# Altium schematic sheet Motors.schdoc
size 298 x 624 mm
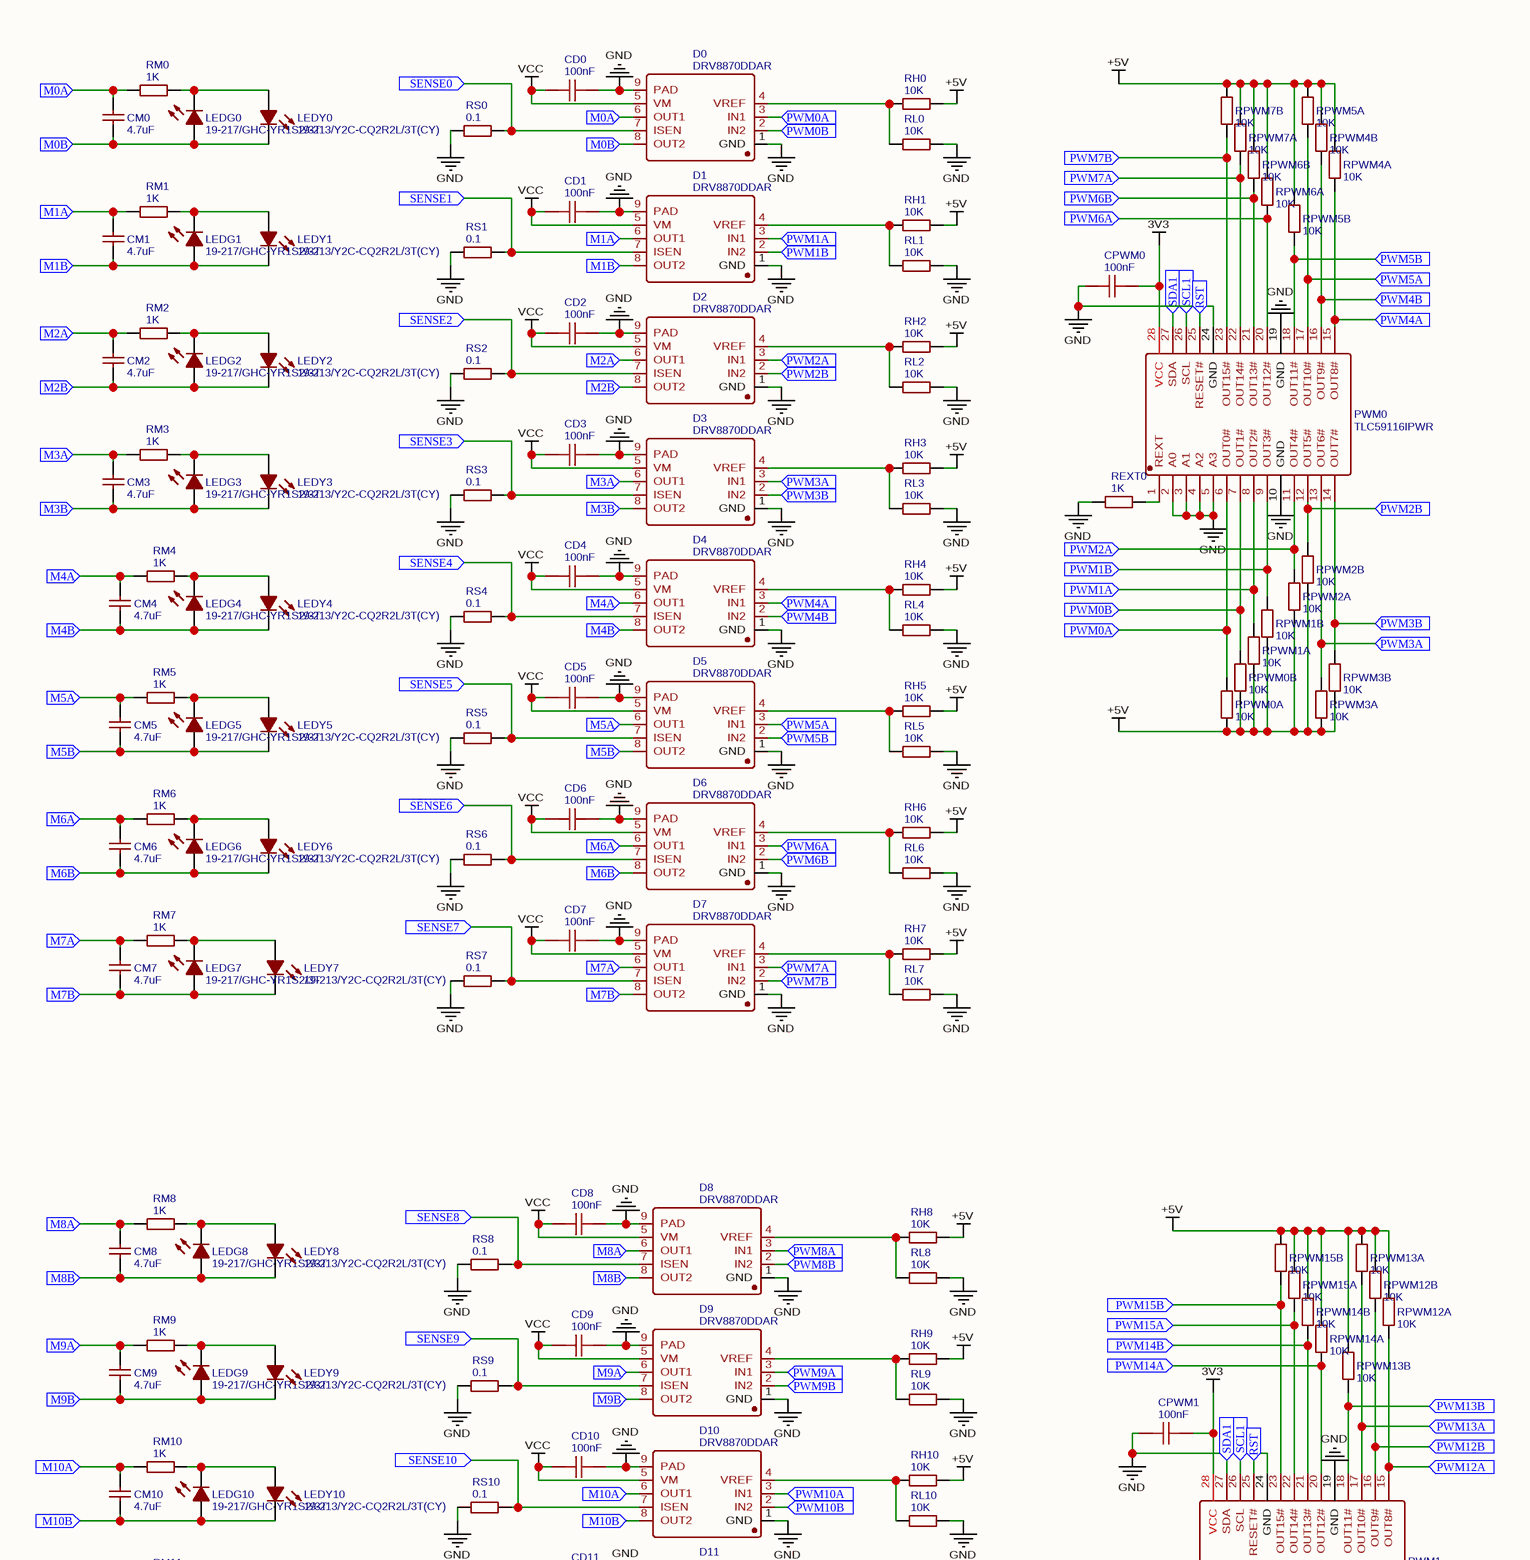
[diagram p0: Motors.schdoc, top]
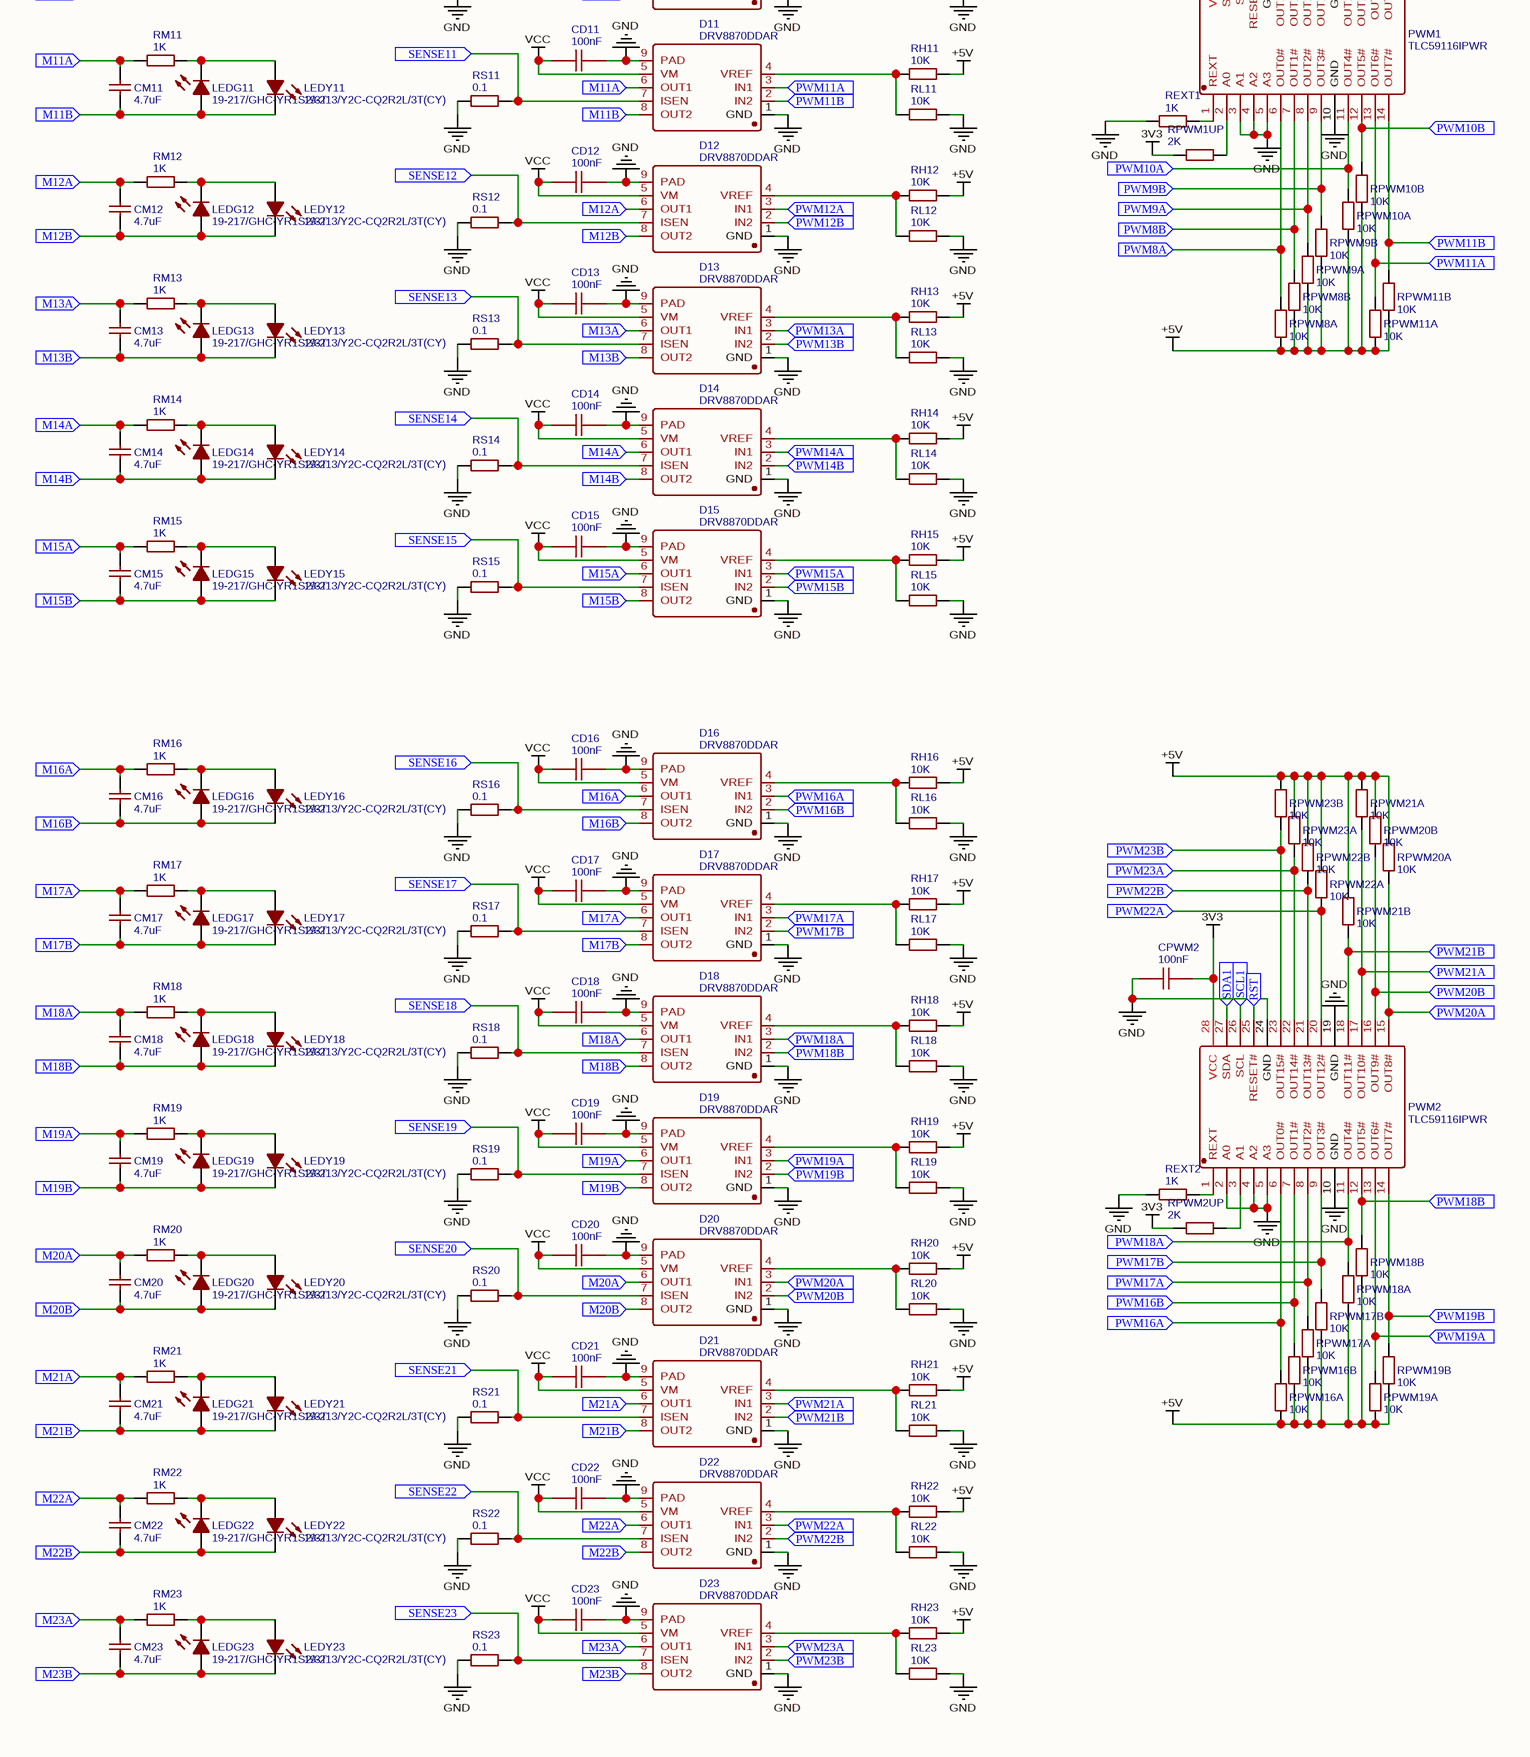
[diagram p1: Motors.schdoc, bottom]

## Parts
CD0  100nF  [0603]
CD1  100nF  [0603]
CD2  100nF  [0603]
CD3  100nF  [0603]
CD4  100nF  [0603]
CD5  100nF  [0603]
CD6  100nF  [0603]
CD7  100nF  [0603]
CD8  100nF  [0603]
CD9  100nF  [0603]
CD10  100nF  [0603]
CD11  100nF  [0603]
CD12  100nF  [0603]
CD13  100nF  [0603]
CD14  100nF  [0603]
CD15  100nF  [0603]
CD16  100nF  [0603]
CD17  100nF  [0603]
CD18  100nF  [0603]
CD19  100nF  [0603]
CD20  100nF  [0603]
CD21  100nF  [0603]
CD22  100nF  [0603]
CD23  100nF  [0603]
CM0  4.7uF  [1206]
CM1  4.7uF  [1206]
CM2  4.7uF  [1206]
CM3  4.7uF  [1206]
CM4  4.7uF  [1206]
CM5  4.7uF  [1206]
CM6  4.7uF  [1206]
CM7  4.7uF  [1206]
CM8  4.7uF  [1206]
CM9  4.7uF  [1206]
CM10  4.7uF  [1206]
CM11  4.7uF  [1206]
CM12  4.7uF  [1206]
CM13  4.7uF  [1206]
CM14  4.7uF  [1206]
CM15  4.7uF  [1206]
CM16  4.7uF  [1206]
CM17  4.7uF  [1206]
CM18  4.7uF  [1206]
CM19  4.7uF  [1206]
CM20  4.7uF  [1206]
CM21  4.7uF  [1206]
CM22  4.7uF  [1206]
CM23  4.7uF  [1206]
CPWM0  100nF  [0603]
CPWM1  100nF  [0603]
CPWM2  100nF  [0603]
D0  DRV8870DDAR  [HSOP-8_L5.0-W4.0-P1.27-LS6.2-BL-EP]
D1  DRV8870DDAR  [HSOP-8_L5.0-W4.0-P1.27-LS6.2-BL-EP]
D2  DRV8870DDAR  [HSOP-8_L5.0-W4.0-P1.27-LS6.2-BL-EP]
D3  DRV8870DDAR  [HSOP-8_L5.0-W4.0-P1.27-LS6.2-BL-EP]
D4  DRV8870DDAR  [HSOP-8_L5.0-W4.0-P1.27-LS6.2-BL-EP]
D5  DRV8870DDAR  [HSOP-8_L5.0-W4.0-P1.27-LS6.2-BL-EP]
D6  DRV8870DDAR  [HSOP-8_L5.0-W4.0-P1.27-LS6.2-BL-EP]
D7  DRV8870DDAR  [HSOP-8_L5.0-W4.0-P1.27-LS6.2-BL-EP]
D8  DRV8870DDAR  [HSOP-8_L5.0-W4.0-P1.27-LS6.2-BL-EP]
D9  DRV8870DDAR  [HSOP-8_L5.0-W4.0-P1.27-LS6.2-BL-EP]
D10  DRV8870DDAR  [HSOP-8_L5.0-W4.0-P1.27-LS6.2-BL-EP]
D11  DRV8870DDAR  [HSOP-8_L5.0-W4.0-P1.27-LS6.2-BL-EP]
D12  DRV8870DDAR  [HSOP-8_L5.0-W4.0-P1.27-LS6.2-BL-EP]
D13  DRV8870DDAR  [HSOP-8_L5.0-W4.0-P1.27-LS6.2-BL-EP]
D14  DRV8870DDAR  [HSOP-8_L5.0-W4.0-P1.27-LS6.2-BL-EP]
D15  DRV8870DDAR  [HSOP-8_L5.0-W4.0-P1.27-LS6.2-BL-EP]
D16  DRV8870DDAR  [HSOP-8_L5.0-W4.0-P1.27-LS6.2-BL-EP]
D17  DRV8870DDAR  [HSOP-8_L5.0-W4.0-P1.27-LS6.2-BL-EP]
D18  DRV8870DDAR  [HSOP-8_L5.0-W4.0-P1.27-LS6.2-BL-EP]
D19  DRV8870DDAR  [HSOP-8_L5.0-W4.0-P1.27-LS6.2-BL-EP]
D20  DRV8870DDAR  [HSOP-8_L5.0-W4.0-P1.27-LS6.2-BL-EP]
D21  DRV8870DDAR  [HSOP-8_L5.0-W4.0-P1.27-LS6.2-BL-EP]
D22  DRV8870DDAR  [HSOP-8_L5.0-W4.0-P1.27-LS6.2-BL-EP]
D23  DRV8870DDAR  [HSOP-8_L5.0-W4.0-P1.27-LS6.2-BL-EP]
LEDG0  19-217/GHC-YR1S2/3T  [LED0603-R-RD]
LEDG1  19-217/GHC-YR1S2/3T  [LED0603-R-RD]
LEDG2  19-217/GHC-YR1S2/3T  [LED0603-R-RD]
LEDG3  19-217/GHC-YR1S2/3T  [LED0603-R-RD]
LEDG4  19-217/GHC-YR1S2/3T  [LED0603-R-RD]
LEDG5  19-217/GHC-YR1S2/3T  [LED0603-R-RD]
LEDG6  19-217/GHC-YR1S2/3T  [LED0603-R-RD]
LEDG7  19-217/GHC-YR1S2/3T  [LED0603-R-RD]
LEDG8  19-217/GHC-YR1S2/3T  [LED0603-R-RD]
LEDG9  19-217/GHC-YR1S2/3T  [LED0603-R-RD]
LEDG10  19-217/GHC-YR1S2/3T  [LED0603-R-RD]
LEDG11  19-217/GHC-YR1S2/3T  [LED0603-R-RD]
LEDG12  19-217/GHC-YR1S2/3T  [LED0603-R-RD]
LEDG13  19-217/GHC-YR1S2/3T  [LED0603-R-RD]
LEDG14  19-217/GHC-YR1S2/3T  [LED0603-R-RD]
LEDG15  19-217/GHC-YR1S2/3T  [LED0603-R-RD]
LEDG16  19-217/GHC-YR1S2/3T  [LED0603-R-RD]
LEDG17  19-217/GHC-YR1S2/3T  [LED0603-R-RD]
LEDG18  19-217/GHC-YR1S2/3T  [LED0603-R-RD]
LEDG19  19-217/GHC-YR1S2/3T  [LED0603-R-RD]
LEDG20  19-217/GHC-YR1S2/3T  [LED0603-R-RD]
LEDG21  19-217/GHC-YR1S2/3T  [LED0603-R-RD]
LEDG22  19-217/GHC-YR1S2/3T  [LED0603-R-RD]
LEDG23  19-217/GHC-YR1S2/3T  [LED0603-R-RD]
LEDY0  19-213/Y2C-CQ2R2L/3T(CY)  [LED0603-R-RD]
LEDY1  19-213/Y2C-CQ2R2L/3T(CY)  [LED0603-R-RD]
LEDY2  19-213/Y2C-CQ2R2L/3T(CY)  [LED0603-R-RD]
LEDY3  19-213/Y2C-CQ2R2L/3T(CY)  [LED0603-R-RD]
LEDY4  19-213/Y2C-CQ2R2L/3T(CY)  [LED0603-R-RD]
LEDY5  19-213/Y2C-CQ2R2L/3T(CY)  [LED0603-R-RD]
LEDY6  19-213/Y2C-CQ2R2L/3T(CY)  [LED0603-R-RD]
LEDY7  19-213/Y2C-CQ2R2L/3T(CY)  [LED0603-R-RD]
LEDY8  19-213/Y2C-CQ2R2L/3T(CY)  [LED0603-R-RD]
LEDY9  19-213/Y2C-CQ2R2L/3T(CY)  [LED0603-R-RD]
LEDY10  19-213/Y2C-CQ2R2L/3T(CY)  [LED0603-R-RD]
LEDY11  19-213/Y2C-CQ2R2L/3T(CY)  [LED0603-R-RD]
LEDY12  19-213/Y2C-CQ2R2L/3T(CY)  [LED0603-R-RD]
LEDY13  19-213/Y2C-CQ2R2L/3T(CY)  [LED0603-R-RD]
LEDY14  19-213/Y2C-CQ2R2L/3T(CY)  [LED0603-R-RD]
LEDY15  19-213/Y2C-CQ2R2L/3T(CY)  [LED0603-R-RD]
LEDY16  19-213/Y2C-CQ2R2L/3T(CY)  [LED0603-R-RD]
LEDY17  19-213/Y2C-CQ2R2L/3T(CY)  [LED0603-R-RD]
LEDY18  19-213/Y2C-CQ2R2L/3T(CY)  [LED0603-R-RD]
LEDY19  19-213/Y2C-CQ2R2L/3T(CY)  [LED0603-R-RD]
LEDY20  19-213/Y2C-CQ2R2L/3T(CY)  [LED0603-R-RD]
LEDY21  19-213/Y2C-CQ2R2L/3T(CY)  [LED0603-R-RD]
LEDY22  19-213/Y2C-CQ2R2L/3T(CY)  [LED0603-R-RD]
LEDY23  19-213/Y2C-CQ2R2L/3T(CY)  [LED0603-R-RD]
PWM0  TLC59116IPWR  [TSSOP-28_L9.8-W3.0-P0.66-LS6.4-BL]
PWM1  TLC59116IPWR  [TSSOP-28_L9.8-W3.0-P0.66-LS6.4-BL]
PWM2  TLC59116IPWR  [TSSOP-28_L9.8-W3.0-P0.66-LS6.4-BL]
REXT0  1K  [0603]
REXT1  1K  [0603]
REXT2  1K  [0603]
RH0  10K  [0603]
RH1  10K  [0603]
RH2  10K  [0603]
RH3  10K  [0603]
RH4  10K  [0603]
RH5  10K  [0603]
RH6  10K  [0603]
RH7  10K  [0603]
RH8  10K  [0603]
RH9  10K  [0603]
RH10  10K  [0603]
RH11  10K  [0603]
RH12  10K  [0603]
RH13  10K  [0603]
RH14  10K  [0603]
RH15  10K  [0603]
RH16  10K  [0603]
RH17  10K  [0603]
RH18  10K  [0603]
RH19  10K  [0603]
RH20  10K  [0603]
RH21  10K  [0603]
RH22  10K  [0603]
RH23  10K  [0603]
RL0  10K  [0603]
RL1  10K  [0603]
RL2  10K  [0603]
RL3  10K  [0603]
RL4  10K  [0603]
RL5  10K  [0603]
RL6  10K  [0603]
RL7  10K  [0603]
RL8  10K  [0603]
RL9  10K  [0603]
RL10  10K  [0603]
RL11  10K  [0603]
RL12  10K  [0603]
RL13  10K  [0603]
RL14  10K  [0603]
RL15  10K  [0603]
RL16  10K  [0603]
RL17  10K  [0603]
RL18  10K  [0603]
RL19  10K  [0603]
RL20  10K  [0603]
RL21  10K  [0603]
RL22  10K  [0603]
RL23  10K  [0603]
RM0  1K  [0603]
RM1  1K  [0603]
RM2  1K  [0603]
RM3  1K  [0603]
RM4  1K  [0603]
RM5  1K  [0603]
RM6  1K  [0603]
RM7  1K  [0603]
RM8  1K  [0603]
RM9  1K  [0603]
RM10  1K  [0603]
RM11  1K  [0603]
RM12  1K  [0603]
RM13  1K  [0603]
RM14  1K  [0603]
RM15  1K  [0603]
RM16  1K  [0603]
RM17  1K  [0603]
RM18  1K  [0603]
RM19  1K  [0603]
RM20  1K  [0603]
RM21  1K  [0603]
RM22  1K  [0603]
RM23  1K  [0603]
RPWM0A  10K  [0603]
RPWM0B  10K  [0603]
RPWM1A  10K  [0603]
RPWM1B  10K  [0603]
RPWM1UP  2K  [0603]
RPWM2A  10K  [0603]
RPWM2B  10K  [0603]
RPWM2UP  2K  [0603]
RPWM3A  10K  [0603]
RPWM3B  10K  [0603]
RPWM4A  10K  [0603]
RPWM4B  10K  [0603]
RPWM5A  10K  [0603]
RPWM5B  10K  [0603]
RPWM6A  10K  [0603]
RPWM6B  10K  [0603]
RPWM7A  10K  [0603]
RPWM7B  10K  [0603]
RPWM8A  10K  [0603]
RPWM8B  10K  [0603]
RPWM9A  10K  [0603]
RPWM9B  10K  [0603]
RPWM10A  10K  [0603]
RPWM10B  10K  [0603]
RPWM11A  10K  [0603]
RPWM11B  10K  [0603]
RPWM12A  10K  [0603]
RPWM12B  10K  [0603]
RPWM13A  10K  [0603]
RPWM13B  10K  [0603]
RPWM14A  10K  [0603]
RPWM14B  10K  [0603]
RPWM15A  10K  [0603]
RPWM15B  10K  [0603]
RPWM16A  10K  [0603]
RPWM16B  10K  [0603]
RPWM17A  10K  [0603]
RPWM17B  10K  [0603]
RPWM18A  10K  [0603]
RPWM18B  10K  [0603]
RPWM19A  10K  [0603]
RPWM19B  10K  [0603]
RPWM20A  10K  [0603]
RPWM20B  10K  [0603]
RPWM21A  10K  [0603]
RPWM21B  10K  [0603]
RPWM22A  10K  [0603]
RPWM22B  10K  [0603]
RPWM23A  10K  [0603]
RPWM23B  10K  [0603]
RS0  0.1  [2512]
RS1  0.1  [2512]
RS2  0.1  [2512]
RS3  0.1  [2512]
RS4  0.1  [2512]
RS5  0.1  [2512]
RS6  0.1  [2512]
RS7  0.1  [2512]
RS8  0.1  [2512]
RS9  0.1  [2512]
RS10  0.1  [2512]
RS11  0.1  [2512]
RS12  0.1  [2512]
RS13  0.1  [2512]
RS14  0.1  [2512]
RS15  0.1  [2512]
RS16  0.1  [2512]
RS17  0.1  [2512]
RS18  0.1  [2512]
RS19  0.1  [2512]
RS20  0.1  [2512]
RS21  0.1  [2512]
RS22  0.1  [2512]
RS23  0.1  [2512]

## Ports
M0A, M0B, M1A, M1B, M2A, M2B, M3A, M3B, M4A, M4B, M5A, M5B, M6A, M6B, M7A, M7B, M8A, M8B, M9A, M9B, M10A, M10B, M11A, M11B, M12A, M12B, M13A, M13B, M14A, M14B, M15A, M15B, M16A, M16B, M17A, M17B, M18A, M18B, M19A, M19B, M20A, M20B, M21A, M21B, M22A, M22B, M23A, M23B, PWM0A, PWM0B, PWM1A, PWM1B, PWM2A, PWM2B, PWM3A, PWM3B, PWM4A, PWM4B, PWM5A, PWM5B, PWM6A, PWM6B, PWM7A, PWM7B, PWM8A, PWM8B, PWM9A, PWM9B, PWM10A, PWM10B, PWM11A, PWM11B, PWM12A, PWM12B, PWM13A, PWM13B, PWM14A, PWM14B, PWM15A, PWM15B, PWM16A, PWM16B, PWM17A, PWM17B, PWM18A, PWM18B, PWM19A, PWM19B, PWM20A, PWM20B, PWM21A, PWM21B, PWM22A, PWM22B, PWM23A, PWM23B, RST, SCL1, SDA1, SENSE0, SENSE1, SENSE2, SENSE3, SENSE4, SENSE5, SENSE6, SENSE7, SENSE8, SENSE9, SENSE10, SENSE11, SENSE12, SENSE13, SENSE14, SENSE15, SENSE16, SENSE17, SENSE18, SENSE19, SENSE20, SENSE21, SENSE22, SENSE23

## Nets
3V3: CPWM0.1 CPWM1.1 CPWM2.1 PWM0.28(VCC) PWM1.28(VCC) PWM2.28(VCC) RPWM1UP.2 RPWM2UP.2
+5V: RH0.2 RH1.2 RH2.2 RH3.2 RH4.2 RH5.2 RH6.2 RH7.2 RH8.2 RH9.2 RH10.2 RH11.2 RH12.2 RH13.2 RH14.2 RH15.2 RH16.2 RH17.2 RH18.2 RH19.2 RH20.2 RH21.2 RH22.2 RH23.2 RPWM0A.1 RPWM0B.1 RPWM1A.1 RPWM1B.1 RPWM2A.1 RPWM2B.1 RPWM3A.1 RPWM3B.1 RPWM4A.2 RPWM4B.2 RPWM5A.2 RPWM5B.2 RPWM6A.2 RPWM6B.2 RPWM7A.2 RPWM7B.2 RPWM8A.1 RPWM8B.1 RPWM9A.1 RPWM9B.1 RPWM10A.1 RPWM10B.1 RPWM11A.1 RPWM11B.1 RPWM12A.2 RPWM12B.2 RPWM13A.2 RPWM13B.2 RPWM14A.2 RPWM14B.2 RPWM15A.2 RPWM15B.2 RPWM16A.1 RPWM16B.1 RPWM17A.1 RPWM17B.1 RPWM18A.1 RPWM18B.1 RPWM19A.1 RPWM19B.1 RPWM20A.2 RPWM20B.2 RPWM21A.2 RPWM21B.2 RPWM22A.2 RPWM22B.2 RPWM23A.2 RPWM23B.2
GND: CD0.1 CD1.1 CD2.1 CD3.1 CD4.1 CD5.1 CD6.1 CD7.1 CD8.1 CD9.1 CD10.1 CD11.1 CD12.1 CD13.1 CD14.1 CD15.1 CD16.1 CD17.1 CD18.1 CD19.1 CD20.1 CD21.1 CD22.1 CD23.1 CPWM0.2 CPWM1.2 CPWM2.2 D0.1(GND) D0.9(PAD) D1.1(GND) D1.9(PAD) D2.1(GND) D2.9(PAD) D3.1(GND) D3.9(PAD) D4.1(GND) D4.9(PAD) D5.1(GND) D5.9(PAD) D6.1(GND) D6.9(PAD) D7.1(GND) D7.9(PAD) D8.1(GND) D8.9(PAD) D9.1(GND) D9.9(PAD) D10.1(GND) D10.9(PAD) D11.1(GND) D11.9(PAD) D12.1(GND) D12.9(PAD) D13.1(GND) D13.9(PAD) D14.1(GND) D14.9(PAD) D15.1(GND) D15.9(PAD) D16.1(GND) D16.9(PAD) D17.1(GND) D17.9(PAD) D18.1(GND) D18.9(PAD) D19.1(GND) D19.9(PAD) D20.1(GND) D20.9(PAD) D21.1(GND) D21.9(PAD) D22.1(GND) D22.9(PAD) D23.1(GND) D23.9(PAD) PWM0.2(A0) PWM0.3(A1) PWM0.4(A2) PWM0.5(A3) PWM0.10(GND) PWM0.19(GND) PWM0.24(GND) PWM1.3(A1) PWM1.4(A2) PWM1.5(A3) PWM1.10(GND) PWM1.19(GND) PWM1.24(GND) PWM2.2(A0) PWM2.4(A2) PWM2.5(A3) PWM2.10(GND) PWM2.19(GND) PWM2.24(GND) REXT0.1 REXT1.1 REXT2.1 RL0.2 RL1.2 RL2.2 RL3.2 RL4.2 RL5.2 RL6.2 RL7.2 RL8.2 RL9.2 RL10.2 RL11.2 RL12.2 RL13.2 RL14.2 RL15.2 RL16.2 RL17.2 RL18.2 RL19.2 RL20.2 RL21.2 RL22.2 RL23.2 RS0.1 RS1.1 RS2.1 RS3.1 RS4.1 RS5.1 RS6.1 RS7.1 RS8.1 RS9.1 RS10.1 RS11.1 RS12.1 RS13.1 RS14.1 RS15.1 RS16.1 RS17.1 RS18.1 RS19.1 RS20.1 RS21.1 RS22.1 RS23.1
VCC: CD0.2 CD1.2 CD2.2 CD3.2 CD4.2 CD5.2 CD6.2 CD7.2 CD8.2 CD9.2 CD10.2 CD11.2 CD12.2 CD13.2 CD14.2 CD15.2 CD16.2 CD17.2 CD18.2 CD19.2 CD20.2 CD21.2 CD22.2 CD23.2 D0.5(VM) D1.5(VM) D2.5(VM) D3.5(VM) D4.5(VM) D5.5(VM) D6.5(VM) D7.5(VM) D8.5(VM) D9.5(VM) D10.5(VM) D11.5(VM) D12.5(VM) D13.5(VM) D14.5(VM) D15.5(VM) D16.5(VM) D17.5(VM) D18.5(VM) D19.5(VM) D20.5(VM) D21.5(VM) D22.5(VM) D23.5(VM)
M0A: CM0.2 D0.6(OUT1) RM0.1 ; port M0A
M0B: CM0.1 D0.8(OUT2) LEDG0.1(A) LEDY0.2(C) ; port M0B
M1A: CM1.2 D1.6(OUT1) RM1.1 ; port M1A
M1B: CM1.1 D1.8(OUT2) LEDG1.1(A) LEDY1.2(C) ; port M1B
M2A: CM2.2 D2.6(OUT1) RM2.1 ; port M2A
M2B: CM2.1 D2.8(OUT2) LEDG2.1(A) LEDY2.2(C) ; port M2B
M3A: CM3.2 D3.6(OUT1) RM3.1 ; port M3A
M3B: CM3.1 D3.8(OUT2) LEDG3.1(A) LEDY3.2(C) ; port M3B
M4A: CM4.2 D4.6(OUT1) RM4.1 ; port M4A
M4B: CM4.1 D4.8(OUT2) LEDG4.1(A) LEDY4.2(C) ; port M4B
M5A: CM5.2 D5.6(OUT1) RM5.1 ; port M5A
M5B: CM5.1 D5.8(OUT2) LEDG5.1(A) LEDY5.2(C) ; port M5B
M6A: CM6.2 D6.6(OUT1) RM6.1 ; port M6A
M6B: CM6.1 D6.8(OUT2) LEDG6.1(A) LEDY6.2(C) ; port M6B
M7A: CM7.2 D7.6(OUT1) RM7.1 ; port M7A
M7B: CM7.1 D7.8(OUT2) LEDG7.1(A) LEDY7.2(C) ; port M7B
M8A: CM8.2 D8.6(OUT1) RM8.1 ; port M8A
M8B: CM8.1 D8.8(OUT2) LEDG8.1(A) LEDY8.2(C) ; port M8B
M9A: CM9.2 D9.6(OUT1) RM9.1 ; port M9A
M9B: CM9.1 D9.8(OUT2) LEDG9.1(A) LEDY9.2(C) ; port M9B
M10A: CM10.2 D10.6(OUT1) RM10.1 ; port M10A
M10B: CM10.1 D10.8(OUT2) LEDG10.1(A) LEDY10.2(C) ; port M10B
M11A: CM11.2 D11.6(OUT1) RM11.1 ; port M11A
M11B: CM11.1 D11.8(OUT2) LEDG11.1(A) LEDY11.2(C) ; port M11B
M12A: CM12.2 D12.6(OUT1) RM12.1 ; port M12A
M12B: CM12.1 D12.8(OUT2) LEDG12.1(A) LEDY12.2(C) ; port M12B
M13A: CM13.2 D13.6(OUT1) RM13.1 ; port M13A
M13B: CM13.1 D13.8(OUT2) LEDG13.1(A) LEDY13.2(C) ; port M13B
M14A: CM14.2 D14.6(OUT1) RM14.1 ; port M14A
M14B: CM14.1 D14.8(OUT2) LEDG14.1(A) LEDY14.2(C) ; port M14B
M15A: CM15.2 D15.6(OUT1) RM15.1 ; port M15A
M15B: CM15.1 D15.8(OUT2) LEDG15.1(A) LEDY15.2(C) ; port M15B
M16A: CM16.2 D16.6(OUT1) RM16.1 ; port M16A
M16B: CM16.1 D16.8(OUT2) LEDG16.1(A) LEDY16.2(C) ; port M16B
M17A: CM17.2 D17.6(OUT1) RM17.1 ; port M17A
M17B: CM17.1 D17.8(OUT2) LEDG17.1(A) LEDY17.2(C) ; port M17B
M18A: CM18.2 D18.6(OUT1) RM18.1 ; port M18A
M18B: CM18.1 D18.8(OUT2) LEDG18.1(A) LEDY18.2(C) ; port M18B
M19A: CM19.2 D19.6(OUT1) RM19.1 ; port M19A
M19B: CM19.1 D19.8(OUT2) LEDG19.1(A) LEDY19.2(C) ; port M19B
M20A: CM20.2 D20.6(OUT1) RM20.1 ; port M20A
M20B: CM20.1 D20.8(OUT2) LEDG20.1(A) LEDY20.2(C) ; port M20B
M21A: CM21.2 D21.6(OUT1) RM21.1 ; port M21A
M21B: CM21.1 D21.8(OUT2) LEDG21.1(A) LEDY21.2(C) ; port M21B
M22A: CM22.2 D22.6(OUT1) RM22.1 ; port M22A
M22B: CM22.1 D22.8(OUT2) LEDG22.1(A) LEDY22.2(C) ; port M22B
M23A: CM23.2 D23.6(OUT1) RM23.1 ; port M23A
M23B: CM23.1 D23.8(OUT2) LEDG23.1(A) LEDY23.2(C) ; port M23B
PWM0A: D0.3(IN1) PWM0.6(OUT0#) RPWM0A.2 ; port PWM0A
PWM0B: D0.2(IN2) PWM0.7(OUT1#) RPWM0B.2 ; port PWM0B
PWM1A: D1.3(IN1) PWM0.8(OUT2#) RPWM1A.2 ; port PWM1A
PWM1B: D1.2(IN2) PWM0.9(OUT3#) RPWM1B.2 ; port PWM1B
PWM2A: D2.3(IN1) PWM0.11(OUT4#) RPWM2A.2 ; port PWM2A
PWM2B: D2.2(IN2) PWM0.12(OUT5#) RPWM2B.2 ; port PWM2B
PWM3A: D3.3(IN1) PWM0.13(OUT6#) RPWM3A.2 ; port PWM3A
PWM3B: D3.2(IN2) PWM0.14(OUT7#) RPWM3B.2 ; port PWM3B
PWM4A: D4.3(IN1) PWM0.15(OUT8#) RPWM4A.1 ; port PWM4A
PWM4B: D4.2(IN2) PWM0.16(OUT9#) RPWM4B.1 ; port PWM4B
PWM5A: D5.3(IN1) PWM0.17(OUT10#) RPWM5A.1 ; port PWM5A
PWM5B: D5.2(IN2) PWM0.18(OUT11#) RPWM5B.1 ; port PWM5B
PWM6A: D6.3(IN1) PWM0.20(OUT12#) RPWM6A.1 ; port PWM6A
PWM6B: D6.2(IN2) PWM0.21(OUT13#) RPWM6B.1 ; port PWM6B
PWM7A: D7.3(IN1) PWM0.22(OUT14#) RPWM7A.1 ; port PWM7A
PWM7B: D7.2(IN2) PWM0.23(OUT15#) RPWM7B.1 ; port PWM7B
PWM8A: D8.3(IN1) PWM1.6(OUT0#) RPWM8A.2 ; port PWM8A
PWM8B: D8.2(IN2) PWM1.7(OUT1#) RPWM8B.2 ; port PWM8B
PWM9A: D9.3(IN1) PWM1.8(OUT2#) RPWM9A.2 ; port PWM9A
PWM9B: D9.2(IN2) PWM1.9(OUT3#) RPWM9B.2 ; port PWM9B
PWM10A: D10.3(IN1) PWM1.11(OUT4#) RPWM10A.2 ; port PWM10A
PWM10B: D10.2(IN2) PWM1.12(OUT5#) RPWM10B.2 ; port PWM10B
PWM11A: D11.3(IN1) PWM1.13(OUT6#) RPWM11A.2 ; port PWM11A
PWM11B: D11.2(IN2) PWM1.14(OUT7#) RPWM11B.2 ; port PWM11B
PWM12A: D12.3(IN1) PWM1.15(OUT8#) RPWM12A.1 ; port PWM12A
PWM12B: D12.2(IN2) PWM1.16(OUT9#) RPWM12B.1 ; port PWM12B
PWM13A: D13.3(IN1) PWM1.17(OUT10#) RPWM13A.1 ; port PWM13A
PWM13B: D13.2(IN2) PWM1.18(OUT11#) RPWM13B.1 ; port PWM13B
PWM14A: D14.3(IN1) PWM1.20(OUT12#) RPWM14A.1 ; port PWM14A
PWM14B: D14.2(IN2) PWM1.21(OUT13#) RPWM14B.1 ; port PWM14B
PWM15A: D15.3(IN1) PWM1.22(OUT14#) RPWM15A.1 ; port PWM15A
PWM15B: D15.2(IN2) PWM1.23(OUT15#) RPWM15B.1 ; port PWM15B
PWM16A: D16.3(IN1) PWM2.6(OUT0#) RPWM16A.2 ; port PWM16A
PWM16B: D16.2(IN2) PWM2.7(OUT1#) RPWM16B.2 ; port PWM16B
PWM17A: D17.3(IN1) PWM2.8(OUT2#) RPWM17A.2 ; port PWM17A
PWM17B: D17.2(IN2) PWM2.9(OUT3#) RPWM17B.2 ; port PWM17B
PWM18A: D18.3(IN1) PWM2.11(OUT4#) RPWM18A.2 ; port PWM18A
PWM18B: D18.2(IN2) PWM2.12(OUT5#) RPWM18B.2 ; port PWM18B
PWM19A: D19.3(IN1) PWM2.13(OUT6#) RPWM19A.2 ; port PWM19A
PWM19B: D19.2(IN2) PWM2.14(OUT7#) RPWM19B.2 ; port PWM19B
PWM20A: D20.3(IN1) PWM2.15(OUT8#) RPWM20A.1 ; port PWM20A
PWM20B: D20.2(IN2) PWM2.16(OUT9#) RPWM20B.1 ; port PWM20B
PWM21A: D21.3(IN1) PWM2.17(OUT10#) RPWM21A.1 ; port PWM21A
PWM21B: D21.2(IN2) PWM2.18(OUT11#) RPWM21B.1 ; port PWM21B
PWM22A: D22.3(IN1) PWM2.20(OUT12#) RPWM22A.1 ; port PWM22A
PWM22B: D22.2(IN2) PWM2.21(OUT13#) RPWM22B.1 ; port PWM22B
PWM23A: D23.3(IN1) PWM2.22(OUT14#) RPWM23A.1 ; port PWM23A
PWM23B: D23.2(IN2) PWM2.23(OUT15#) RPWM23B.1 ; port PWM23B
RST: PWM0.25(RESET#) PWM1.25(RESET#) PWM2.25(RESET#) ; port RST
SCL1: PWM0.26(SCL) PWM1.26(SCL) PWM2.26(SCL) ; port SCL1
SDA1: PWM0.27(SDA) PWM1.27(SDA) PWM2.27(SDA) ; port SDA1
SENSE0: D0.7(ISEN) RS0.2 ; port SENSE0
SENSE1: D1.7(ISEN) RS1.2 ; port SENSE1
SENSE2: D2.7(ISEN) RS2.2 ; port SENSE2
SENSE3: D3.7(ISEN) RS3.2 ; port SENSE3
SENSE4: D4.7(ISEN) RS4.2 ; port SENSE4
SENSE5: D5.7(ISEN) RS5.2 ; port SENSE5
SENSE6: D6.7(ISEN) RS6.2 ; port SENSE6
SENSE7: D7.7(ISEN) RS7.2 ; port SENSE7
SENSE8: D8.7(ISEN) RS8.2 ; port SENSE8
SENSE9: D9.7(ISEN) RS9.2 ; port SENSE9
SENSE10: D10.7(ISEN) RS10.2 ; port SENSE10
SENSE11: D11.7(ISEN) RS11.2 ; port SENSE11
SENSE12: D12.7(ISEN) RS12.2 ; port SENSE12
SENSE13: D13.7(ISEN) RS13.2 ; port SENSE13
SENSE14: D14.7(ISEN) RS14.2 ; port SENSE14
SENSE15: D15.7(ISEN) RS15.2 ; port SENSE15
SENSE16: D16.7(ISEN) RS16.2 ; port SENSE16
SENSE17: D17.7(ISEN) RS17.2 ; port SENSE17
SENSE18: D18.7(ISEN) RS18.2 ; port SENSE18
SENSE19: D19.7(ISEN) RS19.2 ; port SENSE19
SENSE20: D20.7(ISEN) RS20.2 ; port SENSE20
SENSE21: D21.7(ISEN) RS21.2 ; port SENSE21
SENSE22: D22.7(ISEN) RS22.2 ; port SENSE22
SENSE23: D23.7(ISEN) RS23.2 ; port SENSE23
NetD0_4: D0.4(VREF) RH0.1 RL0.1
NetD1_4: D1.4(VREF) RH1.1 RL1.1
NetD2_4: D2.4(VREF) RH2.1 RL2.1
NetD3_4: D3.4(VREF) RH3.1 RL3.1
NetD4_4: D4.4(VREF) RH4.1 RL4.1
NetD5_4: D5.4(VREF) RH5.1 RL5.1
NetD6_4: D6.4(VREF) RH6.1 RL6.1
NetD7_4: D7.4(VREF) RH7.1 RL7.1
NetD8_4: D8.4(VREF) RH8.1 RL8.1
NetD9_4: D9.4(VREF) RH9.1 RL9.1
NetD10_4: D10.4(VREF) RH10.1 RL10.1
NetD11_4: D11.4(VREF) RH11.1 RL11.1
NetD12_4: D12.4(VREF) RH12.1 RL12.1
NetD13_4: D13.4(VREF) RH13.1 RL13.1
NetD14_4: D14.4(VREF) RH14.1 RL14.1
NetD15_4: D15.4(VREF) RH15.1 RL15.1
NetD16_4: D16.4(VREF) RH16.1 RL16.1
NetD17_4: D17.4(VREF) RH17.1 RL17.1
NetD18_4: D18.4(VREF) RH18.1 RL18.1
NetD19_4: D19.4(VREF) RH19.1 RL19.1
NetD20_4: D20.4(VREF) RH20.1 RL20.1
NetD21_4: D21.4(VREF) RH21.1 RL21.1
NetD22_4: D22.4(VREF) RH22.1 RL22.1
NetD23_4: D23.4(VREF) RH23.1 RL23.1
NetLEDG0_2: LEDG0.2(C) LEDY0.1(A) RM0.2
NetLEDG1_2: LEDG1.2(C) LEDY1.1(A) RM1.2
NetLEDG2_2: LEDG2.2(C) LEDY2.1(A) RM2.2
NetLEDG3_2: LEDG3.2(C) LEDY3.1(A) RM3.2
NetLEDG4_2: LEDG4.2(C) LEDY4.1(A) RM4.2
NetLEDG5_2: LEDG5.2(C) LEDY5.1(A) RM5.2
NetLEDG6_2: LEDG6.2(C) LEDY6.1(A) RM6.2
NetLEDG7_2: LEDG7.2(C) LEDY7.1(A) RM7.2
NetLEDG8_2: LEDG8.2(C) LEDY8.1(A) RM8.2
NetLEDG9_2: LEDG9.2(C) LEDY9.1(A) RM9.2
NetLEDG10_2: LEDG10.2(C) LEDY10.1(A) RM10.2
NetLEDG11_2: LEDG11.2(C) LEDY11.1(A) RM11.2
NetLEDG12_2: LEDG12.2(C) LEDY12.1(A) RM12.2
NetLEDG13_2: LEDG13.2(C) LEDY13.1(A) RM13.2
NetLEDG14_2: LEDG14.2(C) LEDY14.1(A) RM14.2
NetLEDG15_2: LEDG15.2(C) LEDY15.1(A) RM15.2
NetLEDG16_2: LEDG16.2(C) LEDY16.1(A) RM16.2
NetLEDG17_2: LEDG17.2(C) LEDY17.1(A) RM17.2
NetLEDG18_2: LEDG18.2(C) LEDY18.1(A) RM18.2
NetLEDG19_2: LEDG19.2(C) LEDY19.1(A) RM19.2
NetLEDG20_2: LEDG20.2(C) LEDY20.1(A) RM20.2
NetLEDG21_2: LEDG21.2(C) LEDY21.1(A) RM21.2
NetLEDG22_2: LEDG22.2(C) LEDY22.1(A) RM22.2
NetLEDG23_2: LEDG23.2(C) LEDY23.1(A) RM23.2
NetPWM0_1: PWM0.1(REXT) REXT0.2
NetPWM1_1: PWM1.1(REXT) REXT1.2
NetPWM1_2: PWM1.2(A0) RPWM1UP.1
NetPWM2_1: PWM2.1(REXT) REXT2.2
NetPWM2_3: PWM2.3(A1) RPWM2UP.1

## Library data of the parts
CD0-CD23 CPWM0-CPWM2 = 100nF: BOM_Manufacturer: YAGEO; BOM_Manufacturer Part: CC0603KRX7R9BB104; nameAlias: Capacitance; SMT Type: Basic
CM0-CM23 = 4.7uF: BOM_Manufacturer: FH; BOM_Manufacturer Part: 1206B475K500NT; nameAlias: Capacitance; SMT Type: Basic
D0-D23 = DRV8870DDAR: BOM_Manufacturer: TI
LEDG0-LEDG23 = 19-217/GHC-YR1S2/3T: BOM_Manufacturer: EVERLIGHT; SMT Type: Basic
LEDY0-LEDY23 = 19-213/Y2C-CQ2R2L/3T(CY): BOM_Manufacturer: EVERLIGHT; SMT Type: Basic
PWM0-PWM2 = TLC59116IPWR: BOM_Manufacturer: TI; SMT Type: Extend
REXT0-REXT2 RM0-RM23 = 1K: BOM_Manufacturer: UniOhm; BOM_Manufacturer Part: 0603WAF1001T5E; nameAlias: Resistance (Ohms); SMT Type: Basic
RH0-RH23 RL0-RL23 RPWM0A RPWM0B RPWM1A RPWM1B RPWM2A RPWM2B RPWM3A RPWM3B RPWM4A RPWM4B RPWM5A RPWM5B RPWM6A RPWM6B RPWM7A RPWM7B RPWM8A RPWM8B RPWM9A RPWM9B RPWM10A RPWM10B RPWM11A RPWM11B RPWM12A RPWM12B RPWM13A RPWM13B RPWM14A RPWM14B RPWM15A RPWM15B RPWM16A RPWM16B RPWM17A RPWM17B RPWM18A RPWM18B RPWM19A RPWM19B RPWM20A RPWM20B RPWM21A RPWM21B RPWM22A RPWM22B RPWM23A RPWM23B = 10K: BOM_Manufacturer: UniOhm; BOM_Manufacturer Part: 0603WAF1002T5E; nameAlias: Resistance (Ohms); SMT Type: Basic
RPWM1UP RPWM2UP = 2K: BOM_Manufacturer: UniOhm; BOM_Manufacturer Part: 0603WAF2001T5E; nameAlias: Resistance (Ohms); SMT Type: Basic
RS0-RS23 = 0.1: BOM_Manufacturer Part: MS122WF100LT4E; BOM_Manufacturer: UniOhm; nameAlias: Resistance (Ohms); SMT Type: Extend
